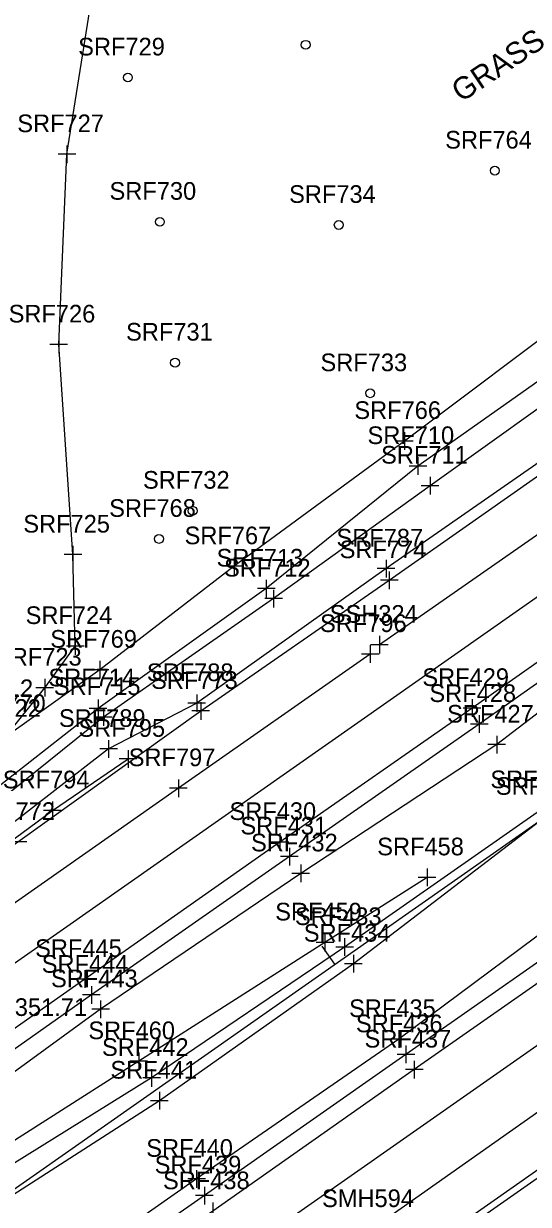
# Model space of a CAD drawing. Extents: x 941041 to 969446, y 397014 to 416764.
# Drawn here: x 951932.7 to 952047.1, y 403287.7 to 403555.2 of the extents above; entities that cross this region are included whole.
import ezdxf

# ---------------------------------------------------------------- set-up
doc = ezdxf.new("R2010")
doc.units = 0
for name, color, linetype in [('SURVEY - CENTERLINE - Preliminary', 7, 'Continuous'), ('SURVEY - CENTERLINE - Preliminary Curve Text', 7, 'Continuous'), ('SURVEY - DRAINAGE - Area Shapes', 7, 'Continuous'), ('SURVEY - DTM - Breaklines', 7, 'Continuous'), ('SURVEY - DTM - Breaklines - Points - Locators', 7, 'Continuous'), ('SURVEY - DTM - Breaklines - Points - Numbers', 7, 'Continuous'), ('SURVEY - DTM - Spot Points - Locators', 7, 'Continuous'), ('SURVEY - DTM - Spot Points - Point Numbers', 7, 'Continuous'), ('SURVEY - ROADSIDE BARRIERS - Points - Locators', 7, 'Continuous'), ('SURVEY - ROADSIDE BARRIERS - Points - Numbers', 7, 'Continuous'), ('SURVEY - ROADSIDE BARRIERS with Text', 7, 'Continuous'), ('SURVEY - TRAFFIC CONTROL - Pavement Marking - Points - Elevations', 7, 'Continuous'), ('SURVEY - TRANSPORTATION - Features', 7, 'Continuous'), ('SURVEY - TRANSPORTATION - Features - Points - Locators', 7, 'Continuous'), ('SURVEY - TRANSPORTATION - Features - Points - Numbers', 7, 'Continuous'), ('SURVEY - TRANSPORTATION - Roads', 7, 'Continuous'), ('SURVEY - TRANSPORTATION - Roads - Points - Locators', 7, 'Continuous'), ('SURVEY - TRANSPORTATION - Roads - Points - Numbers', 7, 'Continuous'), ('SURVEY - VEGETATION - Features with Text', 7, 'Continuous')]:
    doc.layers.add(name, color=color, linetype=linetype)

msp = doc.modelspace()

# ---------------------------------------------------------------- linework, layer by layer
at = {"layer": 'SURVEY - CENTERLINE - Preliminary'}
msp.add_line((950966.25, 402614.81), (953884.31, 404661.52), dxfattribs=at)
msp.add_line((950966.25, 402614.81), (953884.31, 404661.52), dxfattribs=at)
msp.add_line((950966.25, 402614.81), (953884.31, 404661.52), dxfattribs=at)
at = {"layer": 'SURVEY - CENTERLINE - Preliminary Curve Text'}
msp.add_line((952003.23, 403342.14), (952000.36, 403346.23), dxfattribs=at)
at = {"layer": 'SURVEY - DRAINAGE - Area Shapes'}
for points in [[(951145.6, 402792.15), (951562.19, 403084.02), (952475.83, 403724.71), (952754.77, 403922.8), (952578.99, 403846.21), (952455.44, 403792), (952334.19, 403750.29), (951972.51, 403632.53), (951887.41, 403584.59)], [(950765.73, 402528.11), (950855.07, 402487.28), (951056.09, 402625.14), (951609.08, 403015.7), (952524.78, 403657.05), (952475.83, 403724.71)]]:
    msp.add_lwpolyline(points, dxfattribs=at)
at = {"layer": 'SURVEY - DTM - Breaklines'}
for points in [[(951894.21, 403365.74), (951918.42, 403383.39), (951928.26, 403393.2), (951937.5, 403404.8), (951944.43, 403414.22), (951943.9, 403434.94), (951940.69, 403482.53), (951942.54, 403525.65), (951948.59, 403563.68), (951990.69, 403583.16), (952037.49, 403594.92), (952083.73, 403609.86), (952127.47, 403628.84), (952177.41, 403639.18), (952231.73, 403652.95), (952272.64, 403662.7), (952326.07, 403690.06), (952387.14, 403712.34)], [(952390.12, 403709.29), (952375.16, 403701.7), (952334.33, 403674.35), (952294.07, 403646.32), (952253.05, 403618.96), (952212.11, 403590.26), (952172.46, 403561.93), (952135.01, 403533.38), (952096.67, 403507.49), (952059.44, 403481.45), (952022.03, 403454.99), (951987.68, 403427.24), (951949.6, 403400.09), (951914.89, 403372.9), (951892.43, 403360.97), (951856.04, 403333.4)], [(952385.06, 403709.46), (952353.72, 403690.71), (952314.33, 403662.75), (952269.64, 403633.08), (952235.37, 403610.19), (952199.33, 403583.94), (952159.25, 403555.51), (952115.83, 403525.58), (952073.88, 403500.36), (952059.24, 403490.85), (952018.99, 403460.68), (951980.43, 403432.29), (951950.02, 403408.86), (951929.51, 403394.29)], [(952391.5, 403705.96), (952378.05, 403698.72), (952337.41, 403670), (952297.08, 403641.65), (952256.58, 403614.03), (952216.07, 403585.55), (952175.49, 403557.17), (952136.87, 403530.93), (952099.06, 403503.27), (952062.19, 403477.29), (952024.78, 403450.56), (951989.35, 403424.97), (951950.82, 403398.13), (951916.7, 403370.68), (951892.31, 403352.03), (951855.51, 403329.45)], [(952483.82, 403681.92), (952427.27, 403642.38), (952380.72, 403610.67), (952332.46, 403575.38), (952287.62, 403545.12), (952237.01, 403508.6), (952191.86, 403480), (952144.06, 403444.49), (952098.2, 403411.83), (952049.8, 403377.02), (952005.42, 403346.02), (951961.72, 403316.38), (951908.1, 403283.08), (951836.08, 403227.91)], [(952485.25, 403679.95), (952429.13, 403639.43), (952382.71, 403607.61), (952334.17, 403572.43), (952289.83, 403541.57), (952238.45, 403506.07), (952195.26, 403475.23), (952146.22, 403440.76), (952099.32, 403409.75), (952050.92, 403375.53), (952007.43, 403342.26), (951963.47, 403311.23), (951910.97, 403277.41), (951839.65, 403222.38)]]:
    msp.add_lwpolyline(points, dxfattribs=at)
at = {"layer": 'SURVEY - DTM - Breaklines - Points - Locators'}
for p, q in [((951942.54, 403527.65), (951942.54, 403523.65)), ((951944.54, 403525.65), (951940.54, 403525.65)), ((951940.69, 403484.53), (951940.69, 403480.53)), ((951942.69, 403482.53), (951938.69, 403482.53)), ((952018.99, 403462.68), (952018.99, 403458.68)), ((952020.99, 403460.68), (952016.99, 403460.68)), ((952022.03, 403456.99), (952022.03, 403452.99)), ((952024.03, 403454.99), (952020.03, 403454.99)), ((952024.78, 403452.56), (952024.78, 403448.56)), ((952026.78, 403450.56), (952022.78, 403450.56)), ((951945.9, 403434.94), (951941.9, 403434.94)), ((951943.9, 403436.94), (951943.9, 403432.94)), ((951982.43, 403432.29), (951978.43, 403432.29)), ((951980.43, 403434.29), (951980.43, 403430.29)), ((951989.68, 403427.24), (951985.68, 403427.24)), ((951987.68, 403429.24), (951987.68, 403425.24)), ((951989.35, 403426.97), (951989.35, 403422.97)), ((951991.35, 403424.97), (951987.35, 403424.97)), ((951944.43, 403416.22), (951944.43, 403412.22)), ((951946.43, 403414.22), (951942.43, 403414.22)), ((951950.02, 403410.86), (951950.02, 403406.86)), ((951952.02, 403408.86), (951948.02, 403408.86)), ((951937.5, 403406.8), (951937.5, 403402.8)), ((951939.5, 403404.8), (951935.5, 403404.8)), ((951951.6, 403400.09), (951947.6, 403400.09)), ((951949.6, 403402.09), (951949.6, 403398.09)), ((951950.82, 403400.13), (951950.82, 403396.13)), ((951952.82, 403398.13), (951948.82, 403398.13)), ((952005.42, 403348.02), (952005.42, 403344.02)), ((952007.42, 403346.02), (952003.42, 403346.02)), ((952007.43, 403344.26), (952007.43, 403340.26)), ((952009.43, 403342.26), (952005.43, 403342.26)), ((951961.72, 403318.38), (951961.72, 403314.38)), ((951963.72, 403316.38), (951959.72, 403316.38)), ((951963.47, 403313.23), (951963.47, 403309.23)), ((951965.47, 403311.23), (951961.47, 403311.23))]:
    msp.add_line(p, q, dxfattribs=at)
at = {"layer": 'SURVEY - DTM - Spot Points - Locators'}
for centre in [(951996.6, 403550.45), (951956.35, 403543.03), (952039.45, 403521.93), (951963.6, 403510.34), (952004.1, 403509.63), (951967.03, 403478.43), (952011.21, 403471.5), (951971.01, 403444.88), (951963.39, 403438.5)]:
    msp.add_circle(centre, 1, dxfattribs=at)
at = {"layer": 'SURVEY - ROADSIDE BARRIERS - Points - Locators'}
for p, q in [((951956.4, 403390.67), (951956.4, 403386.67)), ((951958.4, 403388.67), (951954.4, 403388.67)), ((951939.26, 403378.99), (951939.26, 403374.99)), ((951941.26, 403376.99), (951937.26, 403376.99)), ((952024.11, 403363.82), (952024.11, 403359.82)), ((952026.11, 403361.82), (952022.11, 403361.82)), ((952002.98, 403347.06), (951998.98, 403347.06)), ((952000.98, 403349.06), (952000.98, 403345.06)), ((951960.8, 403320.17), (951956.8, 403320.17)), ((951958.8, 403322.17), (951958.8, 403318.17))]:
    msp.add_line(p, q, dxfattribs=at)
at = {"layer": 'SURVEY - ROADSIDE BARRIERS with Text'}
for points in [[(951886.07, 403338.53), (951913.72, 403358.18), (951939.26, 403376.99), (951956.4, 403388.67)], [(952024.11, 403361.82), (952000.98, 403347.06), (951958.8, 403320.17), (951916.65, 403293.27), (951886.06, 403273.2), (951843.69, 403243.55)]]:
    msp.add_lwpolyline(points, dxfattribs=at)
at = {"layer": 'SURVEY - TRANSPORTATION - Features'}
for points in [[(952645.64, 403820.24), (952597.37, 403785.52), (952553.07, 403755.16), (952508.33, 403722.84), (952461.02, 403689.31), (952413.89, 403656.85), (952372.14, 403627.74), (952321.41, 403592.67), (952277.52, 403560.71), (952227.07, 403525.98), (952181.35, 403493.84), (952134.56, 403460.33), (952087.52, 403428.37), (952039.89, 403391.89), (951995.48, 403362.71), (951950.18, 403331.94), (951900.76, 403296.02), (951846.55, 403258.26)], [(952622.56, 403749.53), (952577.8, 403717.92), (952532.08, 403686.84), (952486.03, 403653.05), (952440.27, 403622.51), (952394.74, 403590.13), (952344.15, 403555.61), (952299.81, 403523.27), (952250.2, 403489.24), (952206.86, 403458.08), (952156.3, 403423.75), (952110.49, 403390.56), (952062.35, 403358.41), (952017.69, 403325.18), (951971.92, 403293.52), (951916.96, 403254.99), (951879.97, 403228.71), (951856.72, 403212.68)], [(952265.24, 403606.38), (952222.49, 403576.23), (952179.99, 403546.98), (952139.51, 403518.29), (952098.53, 403490.18), (952058.63, 403462.26), (952014.83, 403431.77), (951971.94, 403401.29), (951951.98, 403390.91), (951922.49, 403368.14), (951893.1, 403345.72), (951854.25, 403319.66)], [(952356.31, 403508.85), (952319.54, 403482.53), (952271.2, 403449.46), (952218.02, 403412.1), (952168.51, 403377.19), (952118.64, 403342.5), (952070.41, 403308.53), (952018.6, 403272.33), (951969.85, 403238.11), (951920.07, 403203.33), (951882.16, 403176.11), (951845.47, 403150.79)]]:
    msp.add_lwpolyline(points, dxfattribs=at)
at = {"layer": 'SURVEY - TRANSPORTATION - Features - Points - Locators'}
for p, q in [((952014.83, 403433.77), (952014.83, 403429.77)), ((952016.83, 403431.77), (952012.83, 403431.77)), ((951971.94, 403403.29), (951971.94, 403399.29)), ((951973.94, 403401.29), (951969.94, 403401.29)), ((951951.98, 403392.91), (951951.98, 403388.91)), ((952039.89, 403393.89), (952039.89, 403389.89)), ((951953.98, 403390.91), (951949.98, 403390.91)), ((952041.89, 403391.89), (952037.89, 403391.89)), ((951997.48, 403362.71), (951993.48, 403362.71)), ((951995.48, 403364.71), (951995.48, 403360.71)), ((951950.18, 403333.94), (951950.18, 403329.94)), ((951952.18, 403331.94), (951948.18, 403331.94)), ((952019.69, 403325.18), (952015.69, 403325.18)), ((952017.69, 403327.18), (952017.69, 403323.18)), ((951973.92, 403293.52), (951969.92, 403293.52)), ((951971.92, 403295.52), (951971.92, 403291.52))]:
    msp.add_line(p, q, dxfattribs=at)
at = {"layer": 'SURVEY - TRANSPORTATION - Roads'}
for points in [[(952697.16, 403893.97), (952641.04, 403854.87), (952584.14, 403814.78), (952532.55, 403778.68), (952481.32, 403742.62), (952431.11, 403707.16), (952375.85, 403668.53), (952325.36, 403633.08), (952273.9, 403596.95), (952221.23, 403559.82), (952172.53, 403526.04), (952120.87, 403489.74), (952069.02, 403453.35), (952013.3, 403414.51)], [(952641.53, 403826.17), (952594.17, 403793.02), (952548.96, 403761.1), (952503.9, 403729.55), (952456.48, 403696.45), (952409.67, 403663.54), (952367.99, 403634.29), (952317.16, 403598.59), (952272.62, 403567.27), (952222.63, 403532.35), (952176.87, 403500.19), (952130.48, 403467.59), (952084.27, 403435.24), (952034.3, 403400.18), (951990.77, 403369.82), (951946.58, 403338.79), (951896.13, 403303.32), (951845.2, 403267.54)], [(952643.61, 403822.77), (952594.67, 403788.44), (952551.07, 403757.87), (952505.87, 403726.23), (952458.48, 403693.09), (952411.72, 403660.12), (952370.22, 403630.98), (952318.83, 403594.87), (952274.8, 403564.01), (952224.59, 403528.84), (952179.21, 403496.84), (952131.71, 403463.73), (952086.34, 403432.04), (952035.93, 403396.55), (951992.92, 403366.55), (951948.08, 403335.21), (951898.42, 403300.16), (951843.97, 403261.96)], [(952625.22, 403746.95), (952579.91, 403715.1), (952534.83, 403683.49), (952487.43, 403650.41), (952442.83, 403619.09), (952396.91, 403586.46), (952346.61, 403551.28), (952301.65, 403519.95), (952253.11, 403485.53), (952208.83, 403454.47), (952159.44, 403419.8), (952112.68, 403387.11), (952066.16, 403354.45), (952019.33, 403321.73), (951973.66, 403289.75), (951918.65, 403251.32), (951882.81, 403225.68), (951856.94, 403208.02)], [(952627.47, 403743.75), (952581.75, 403711.66), (952537.07, 403680.23), (952488.75, 403646.32), (952445.47, 403615.87), (952397.1, 403581.89), (952349.33, 403548.4), (952302.96, 403515.9), (952255.29, 403482.36), (952210.22, 403450.79), (952161.93, 403416.95), (952113.95, 403383.26), (952068.49, 403351.38), (952021.19, 403318.27), (951975.59, 403286.18), (951920.11, 403247.28), (951884.29, 403222.24), (951858.06, 403203.77)], [(951856.58, 403318.44), (951891.45, 403341.66), (951931.45, 403369.84), (951972.85, 403399.52), (952015.55, 403429.14), (952058.97, 403459.69), (952101.7, 403489.65), (952145.9, 403520.52), (952190.22, 403551.62), (952232.61, 403581.27), (952267.1, 403605.5)], [(952447.34, 403587.64), (952403.74, 403556.93), (952357.95, 403524.8), (952311.77, 403492.65), (952264.09, 403459.22), (952211.18, 403421.94), (952159.19, 403385.58), (952111.45, 403351.91), (952063.96, 403319.03), (952011.56, 403282.13), (951962.38, 403247.78), (951912.18, 403212.48), (951876.49, 403187.38), (951846.26, 403165.91)], [(952363.66, 403516.11), (952318.6, 403484.64), (952270.5, 403450.6), (952217.03, 403413.11), (952165.82, 403377.48), (952117.66, 403343.68), (952069.64, 403309.92), (952017.59, 403273.34), (951968.61, 403239.23), (951919.39, 403204.95), (951881.03, 403178.29), (951848.45, 403157.23)], [(952011.22, 403412.4), (951967.78, 403382.02), (951890.38, 403327.71), (951852.43, 403301)]]:
    msp.add_lwpolyline(points, dxfattribs=at)
at = {"layer": 'SURVEY - TRANSPORTATION - Roads - Points - Locators'}
for p, q in [((952015.55, 403431.14), (952015.55, 403427.14)), ((952017.55, 403429.14), (952013.55, 403429.14)), ((952013.3, 403416.51), (952013.3, 403412.51)), ((952011.22, 403414.4), (952011.22, 403410.4)), ((952015.3, 403414.51), (952011.3, 403414.51)), ((952013.22, 403412.4), (952009.22, 403412.4)), ((951972.85, 403401.52), (951972.85, 403397.52)), ((952036.3, 403400.18), (952032.3, 403400.18)), ((952034.3, 403402.18), (952034.3, 403398.18)), ((951974.85, 403399.52), (951970.85, 403399.52)), ((952035.93, 403398.55), (952035.93, 403394.55)), ((952037.93, 403396.55), (952033.93, 403396.55)), ((951967.78, 403384.02), (951967.78, 403380.02)), ((951969.78, 403382.02), (951965.78, 403382.02)), ((951990.77, 403371.82), (951990.77, 403367.82)), ((951933.45, 403369.84), (951929.45, 403369.84)), ((951992.77, 403369.82), (951988.77, 403369.82)), ((951992.92, 403368.55), (951992.92, 403364.55)), ((951994.92, 403366.55), (951990.92, 403366.55)), ((951948.58, 403338.79), (951944.58, 403338.79)), ((951946.58, 403340.79), (951946.58, 403336.79)), ((951948.08, 403337.21), (951948.08, 403333.21)), ((951950.08, 403335.21), (951946.08, 403335.21)), ((952019.33, 403323.73), (952019.33, 403319.73)), ((952021.33, 403321.73), (952017.33, 403321.73)), ((952021.19, 403320.27), (952021.19, 403316.27)), ((952023.19, 403318.27), (952019.19, 403318.27)), ((951973.66, 403291.75), (951973.66, 403287.75)), ((951975.66, 403289.75), (951971.66, 403289.75)), ((951975.59, 403288.18), (951975.59, 403284.18))]:
    msp.add_line(p, q, dxfattribs=at)

# ---------------------------------------------------------------- texts
at = {"layer": 'SURVEY - DTM - Breaklines - Points - Numbers'}
for s, p in [('SRF727', (951931.3, 403530.65)), ('SRF726', (951929.34, 403487.53)), ('SRF766', (952007.64, 403465.68)), ('SRF710', (952010.62, 403459.99)), ('SRF711', (952013.7, 403455.56)), ('SRF725', (951932.66, 403439.94)), ('SRF767', (951969.19, 403437.29)), ('SRF713', (951976.44, 403432.24)), ('SRF712', (951978.11, 403429.97)), ('SRF724', (951933.19, 403419.22)), ('SRF769', (951938.77, 403413.86)), ('SRF723', (951926.26, 403409.8)), ('SRF714', (951938.36, 403405.09)), ('SRF715', (951939.58, 403403.13)), ('SRF770', (951918.1, 403399.29)), ('SRF722', (951917.02, 403398.2)), ('SRF426', (952038.45, 403382.02)), ('SRF425', (952039.68, 403380.53)), ('SRF433', (951994.18, 403351.02)), ('SRF434', (951996.19, 403347.26)), ('SRF442', (951950.48, 403321.38)), ('SRF441', (951952.39, 403316.23))]:
    msp.add_text(s, height=4, dxfattribs=at).set_placement(p)
at = {"layer": 'SURVEY - DTM - Spot Points - Point Numbers'}
for s, p in [('SRF729', (951945.09, 403548.03)), ('SRF764', (952028.21, 403526.93)), ('SRF730', (951952.19, 403515.34)), ('SRF734', (951992.86, 403514.63)), ('SRF731', (951955.94, 403483.43)), ('SRF733', (951999.97, 403476.5)), ('SRF732', (951959.77, 403449.88)), ('SRF768', (951952.11, 403443.5)), ('SDB912', (951914.97, 403402.66))]:
    msp.add_text(s, height=4, dxfattribs=at).set_placement(p)
at = {"layer": 'SURVEY - ROADSIDE BARRIERS - Points - Numbers'}
for s, p in [('SRF795', (951945.16, 403393.67)), ('SRF794', (951928.02, 403381.99)), ('SRF458', (952012.82, 403366.82)), ('SRF459', (951989.72, 403352.06)), ('SRF460', (951947.39, 403325.17))]:
    msp.add_text(s, height=4, dxfattribs=at).set_placement(p)
at = {"layer": 'SURVEY - TRAFFIC CONTROL - Pavement Marking - Points - Elevations'}
msp.add_text('EL-351.71', height=4, dxfattribs=at).set_placement((951922.41, 403330.43))
at = {"layer": 'SURVEY - TRANSPORTATION - Features - Points - Numbers'}
for s, p in [('SRF787', (952003.59, 403436.77)), ('SRF788', (951960.65, 403406.29)), ('SRF427', (952028.65, 403396.89)), ('SRF789', (951940.73, 403395.91)), ('SRF432', (951984.24, 403367.71)), ('SRF443', (951938.94, 403336.94)), ('SRF435', (952006.45, 403330.18)), ('SRF440', (951960.51, 403298.52))]:
    msp.add_text(s, height=4, dxfattribs=at).set_placement(p)
at = {"layer": 'SURVEY - TRANSPORTATION - Roads - Points - Numbers'}
for s, p in [('SRF774', (952004.31, 403434.14)), ('SRF796', (951999.87, 403417.4)), ('SSH324', (952002.06, 403419.51)), ('SRF773', (951961.61, 403404.52)), ('SRF429', (952023.04, 403405.18)), ('SRF428', (952024.64, 403401.55)), ('SRF797', (951956.54, 403387.02)), ('SRF772', (951920.21, 403374.84)), ('SRF430', (951979.36, 403374.82)), ('SRF431', (951981.84, 403371.55)), ('SRF445', (951935.34, 403343.79)), ('SRF444', (951936.84, 403340.21)), ('SRF436', (952007.99, 403326.73)), ('SRF437', (952009.95, 403323.27)), ('SRF439', (951962.41, 403294.75)), ('SRF438', (951964.3, 403291.18)), ('SMH594', (952000.32, 403287.13))]:
    msp.add_text(s, height=4, dxfattribs=at).set_placement(p)
at = {"layer": 'SURVEY - VEGETATION - Features with Text'}
msp.add_text('GRASS', height=4.998, rotation=33.7585, dxfattribs=at).set_placement((952031.82, 403537.28))

doc.saveas('drawing.dxf')
